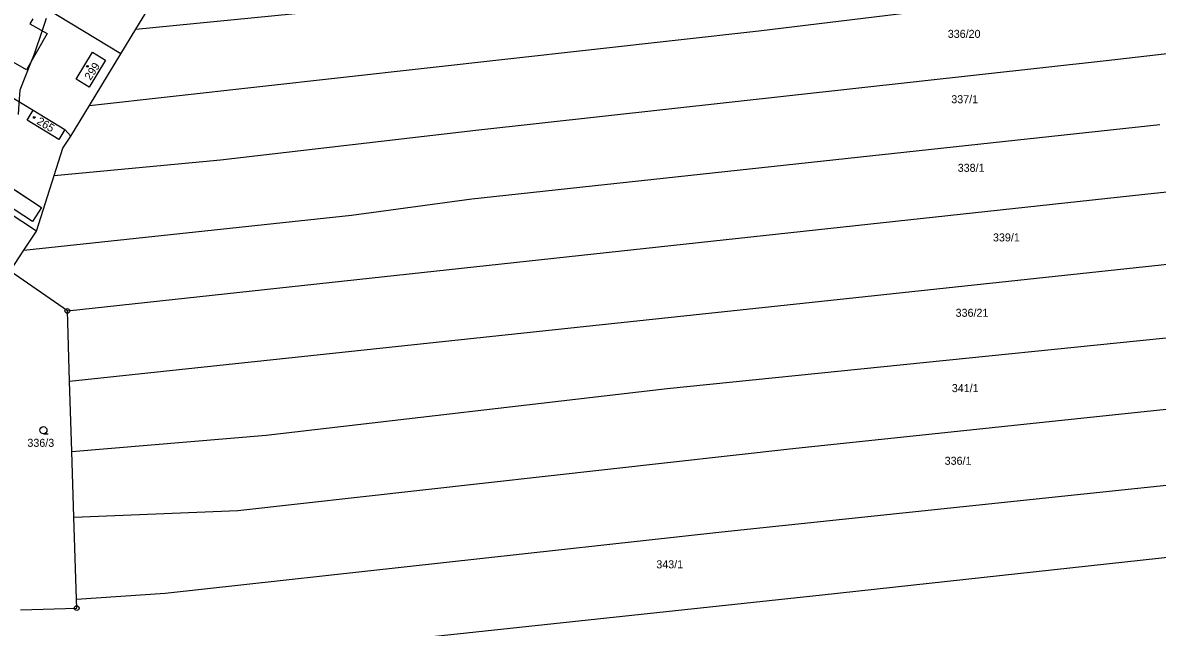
# Model space of a CAD drawing. Extents: x -747333 to -745433, y -1133152 to -1130600.
# Drawn here: x -746224.7 to -745983.7, y -1131989.8 to -1131861.6 of the extents above; entities that cross this region are included whole.
import ezdxf

# ---------------------------------------------------------------- set-up
doc = ezdxf.new("R2010")
doc.units = 0
for name, color, linetype in [('Vrstva 1', 7, 'Continuous'), ('Vrstva 18', 7, 'Continuous'), ('Vrstva 19', 7, 'Continuous'), ('Vrstva 24', 7, 'Continuous'), ('Vrstva 25', 7, 'Continuous'), ('Vrstva 3', 7, 'Continuous'), ('Vrstva 37', 7, 'Continuous'), ('Vrstva 52', 7, 'Continuous'), ('Vrstva 6', 7, 'Continuous')]:
    doc.layers.add(name, color=color, linetype=linetype)

msp = doc.modelspace()

# ---------------------------------------------------------------- linework, layer by layer
at = {"layer": 'Vrstva 1'}
for p, q in [((-746249.25, -1131863.91), (-746222.41, -1131880.1)), ((-746213.32, -1131873.54), (-746209.86, -1131867.8)), ((-746209.86, -1131867.8), (-746207.08, -1131869.48)), ((-746207.08, -1131869.48), (-746210.56, -1131875.2)), ((-746210.56, -1131875.2), (-746213.32, -1131873.54)), ((-746223.7, -1131882.26), (-746222.41, -1131880.1)), ((-746222.41, -1131880.1), (-746215.69, -1131884.18)), ((-746216.98, -1131886.31), (-746223.7, -1131882.26)), ((-746215.69, -1131884.18), (-746216.98, -1131886.31)), ((-746215.69, -1131884.18), (-746214.41, -1131885.62)), ((-746231.67, -1131893.56), (-746220.68, -1131900.75)), ((-746222.59, -1131903.76), (-746233.66, -1131896.54)), ((-746220.68, -1131900.75), (-746222.59, -1131903.76))]:
    msp.add_line(p, q, dxfattribs=at)
for points in [[(-746203.84, -1131868.19), (-746238.83, -1131846.91)], [(-746200.63, -1131862.93), (-746193.13, -1131850.62)], [(-746222.52, -1131860.73), (-746223.11, -1131861.77)], [(-746223.11, -1131861.77), (-746219.47, -1131863.84)], [(-746203.84, -1131868.19), (-746200.63, -1131862.93)], [(-746223.85, -1131871.53), (-746235.4, -1131864.95)], [(-746219.47, -1131863.84), (-746223.85, -1131871.53)], [(-746210.48, -1131879.13), (-746203.84, -1131868.19)], [(-746214.41, -1131885.62), (-746210.48, -1131879.13)], [(-746216.12, -1131888.19), (-746214.41, -1131885.62)], [(-746217.97, -1131893.97), (-746216.12, -1131888.19)], [(-746221.73, -1131905.75), (-746217.97, -1131893.97)], [(-746221.73, -1131905.75), (-746237.77, -1131895.22)], [(-746224.39, -1131909.81), (-746221.73, -1131905.75)], [(-746227.34, -1131914.3), (-746224.39, -1131909.81)], [(-746215.18, -1131922.7), (-746227.34, -1131914.3)], [(-746214.71, -1131937.61), (-746215.18, -1131922.7)], [(-746214.24, -1131952.56), (-746214.71, -1131937.61)], [(-746213.8, -1131966.46), (-746214.24, -1131952.56)], [(-746213.25, -1131983.86), (-746213.8, -1131966.46)], [(-746213.19, -1131985.77), (-746213.25, -1131983.86)], [(-746225.16, -1131986.13), (-746213.19, -1131985.77)]]:
    msp.add_lwpolyline(points, dxfattribs=at)
at = {"layer": 'Vrstva 24'}
for p, q in [((-746215.23, -1131922.7), (-746215.13, -1131922.7)), ((-746213.24, -1131985.77), (-746213.14, -1131985.77))]:
    msp.add_line(p, q, dxfattribs=at)
for centre in [(-746215.18, -1131922.7), (-746213.19, -1131985.77)]:
    msp.add_circle(centre, 0.499289, dxfattribs=at)
at = {"layer": 'Vrstva 25'}
msp.add_line((-746220.26, -1131948.76), (-746219.26, -1131948.76), dxfattribs=at)
for centre, radius in [((-746210.91, -1131870.82), 0.174503), ((-746222.21, -1131881.65), 0.174503), ((-746220.26, -1131948.01), 0.75)]:
    msp.add_circle(centre, radius, dxfattribs=at)
at = {"layer": 'Vrstva 3'}
for points in [[(-746222.52, -1131860.73), (-746223.11, -1131861.77)], [(-746223.11, -1131861.77), (-746219.47, -1131863.84)], [(-746223.85, -1131871.53), (-746235.4, -1131864.95)], [(-746219.47, -1131863.84), (-746223.85, -1131871.53)], [(-746213.32, -1131873.54), (-746209.86, -1131867.8)], [(-746209.86, -1131867.8), (-746207.08, -1131869.48)], [(-746207.08, -1131869.48), (-746210.56, -1131875.2)], [(-746210.56, -1131875.2), (-746213.32, -1131873.54)], [(-746223.7, -1131882.26), (-746222.41, -1131880.1)], [(-746222.41, -1131880.1), (-746215.69, -1131884.18)], [(-746216.98, -1131886.31), (-746223.7, -1131882.26)], [(-746215.69, -1131884.18), (-746216.98, -1131886.31)], [(-746231.67, -1131893.56), (-746220.68, -1131900.75)], [(-746222.59, -1131903.76), (-746233.66, -1131896.54)], [(-746220.68, -1131900.75), (-746222.59, -1131903.76)]]:
    msp.add_lwpolyline(points, dxfattribs=at)
at = {"layer": 'Vrstva 37'}
for centre in [(-746210.91, -1131870.82), (-746222.21, -1131881.65)]:
    msp.add_circle(centre, 0.174503, dxfattribs=at)
at = {"layer": 'Vrstva 52'}
msp.add_lwpolyline([(-746219.69, -1131860.63), (-746220.56, -1131863.22), (-746222.25, -1131868.25), (-746222.85, -1131869.77), (-746225.25, -1131875.88), (-746225.46, -1131878.73), (-746225.63, -1131881)], dxfattribs=at)
at = {"layer": 'Vrstva 6'}
for points in [[(-746068.37, -1131863.25), (-745959.35, -1131849.97)], [(-745994.6, -1131869.54), (-745871.94, -1131855.43)], [(-746200.63, -1131862.93), (-746138, -1131856.68)], [(-746210.48, -1131879.13), (-746068.37, -1131863.25)], [(-746128.44, -1131884.38), (-745994.6, -1131869.54)], [(-746182.66, -1131890.66), (-746128.44, -1131884.38)], [(-746129.29, -1131898.95), (-745983.18, -1131883.12)], [(-745986.39, -1131897.96), (-745877.23, -1131886.38)], [(-746217.97, -1131893.97), (-746182.66, -1131890.66)], [(-746154.83, -1131902.38), (-746129.29, -1131898.95)], [(-746100.74, -1131910.33), (-745986.39, -1131897.96)], [(-746058.97, -1131921.07), (-745881.66, -1131902.09)], [(-746224.39, -1131909.81), (-746154.83, -1131902.38)], [(-746215.18, -1131922.7), (-746100.74, -1131910.33)], [(-745987.44, -1131929), (-745886.79, -1131918.79)], [(-746214.71, -1131937.61), (-746058.97, -1131921.07)], [(-746087.79, -1131939.2), (-745987.44, -1131929)], [(-746061.11, -1131951.9), (-745891.79, -1131934.06)], [(-746172.98, -1131949.05), (-746087.79, -1131939.2)], [(-746214.24, -1131952.56), (-746172.98, -1131949.05)], [(-746178.97, -1131965.04), (-746061.11, -1131951.9)], [(-746076.23, -1131969.6), (-745898.21, -1131950.9)], [(-746213.8, -1131966.46), (-746178.97, -1131965.04)], [(-746054.91, -1131982.95), (-745903.63, -1131966.47)], [(-746194.38, -1131982.59), (-746076.23, -1131969.6)], [(-746223.83, -1132000.95), (-746054.91, -1131982.95)], [(-746213.25, -1131983.86), (-746194.38, -1131982.59)]]:
    msp.add_lwpolyline(points, dxfattribs=at)

# ---------------------------------------------------------------- texts
at = {"layer": 'Vrstva 18'}
for s, p in [('336/20', (-746028.22, -1131864.77)), ('337/1', (-746027.47, -1131878.64)), ('338/1', (-746026.11, -1131893.19)), ('339/1', (-746018.62, -1131907.96)), ('336/21', (-746026.55, -1131923.95)), ('341/1', (-746027.36, -1131939.93)), ('336/3', (-746223.66, -1131951.54)), ('336/1', (-746028.88, -1131955.35)), ('343/1', (-746090.11, -1131977.32))]:
    msp.add_text(s, height=1.7, dxfattribs=at).set_placement(p)
at = {"layer": 'Vrstva 19'}
for s, rotation, p in [('299', 56.19996, (-746210.27, -1131873.89)), ('265', 328.92354, (-746221.822656, -1131882.904248))]:
    msp.add_text(s, height=1.7, rotation=rotation, dxfattribs=at).set_placement(p)

doc.saveas('drawing.dxf')
